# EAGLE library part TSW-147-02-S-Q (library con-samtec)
THROUGH-HOLE .025" SQ POST HEADER Source: Samtec TSW.pdf
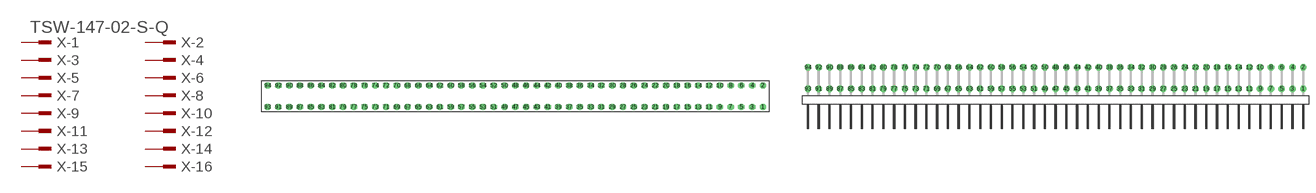
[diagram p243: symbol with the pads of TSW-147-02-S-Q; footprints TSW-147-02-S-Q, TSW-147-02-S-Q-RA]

Designator prefix X; gates -1=MPINV -2=MPIN -3=MPIN -4=MPIN -5=MPIN -6=MPIN -7=MPIN -8=MPIN -9=MPIN -10=MPIN -11=MPIN -12=MPIN -13=MPIN -14=MPIN -15=MPIN -16=MPIN -17=MPIN -18=MPIN -19=MPIN -20=MPIN -21=MPIN -22=MPIN -23=MPIN -24=MPIN -25=MPIN -26=MPIN -27=MPIN -28=MPIN -29=MPIN -30=MPIN -31=MPIN -32=MPIN -33=MPIN -34=MPIN -35=MPIN -36=MPIN -37=MPIN -38=MPIN -39=MPIN -40=MPIN -41=MPIN -42=MPIN -43=MPIN -44=MPIN -45=MPIN -46=MPIN -47=MPIN -48=MPIN -49=MPIN -50=MPIN -51=MPIN -52=MPIN -53=MPIN -54=MPIN -55=MPIN -56=MPIN -57=MPIN -58=MPIN -59=MPIN -60=MPIN -61=MPIN -62=MPIN -63=MPIN -64=MPIN -65=MPIN -66=MPIN -67=MPIN -68=MPIN -69=MPIN -70=MPIN -71=MPIN -72=MPIN -73=MPIN -74=MPIN -75=MPIN -76=MPIN -77=MPIN -78=MPIN -79=MPIN -80=MPIN -81=MPIN -82=MPIN -83=MPIN -84=MPIN -85=MPIN -86=MPIN -87=MPIN -88=MPIN -89=MPIN -90=MPIN -91=MPIN -92=MPIN -93=MPIN -94=MPIN

## TSW-147-02-S-Q (OC_FARNELL: unknown; OC_NEWARK: unknown)  [TSW-147-02-S-Q]
1  -1:1  pas
2  -2:1  pas
3  -3:1  pas
4  -4:1  pas
5  -5:1  pas
6  -6:1  pas
7  -7:1  pas
8  -8:1  pas
9  -9:1  pas
10  -10:1  pas
11  -11:1  pas
12  -12:1  pas
13  -13:1  pas
14  -14:1  pas
15  -15:1  pas
16  -16:1  pas
17  -17:1  pas
18  -18:1  pas
19  -19:1  pas
20  -20:1  pas
21  -21:1  pas
22  -22:1  pas
23  -23:1  pas
24  -24:1  pas
25  -25:1  pas
26  -26:1  pas
27  -27:1  pas
28  -28:1  pas
29  -29:1  pas
30  -30:1  pas
31  -31:1  pas
32  -32:1  pas
33  -33:1  pas
34  -34:1  pas
35  -35:1  pas
36  -36:1  pas
37  -37:1  pas
38  -38:1  pas
39  -39:1  pas
40  -40:1  pas
41  -41:1  pas
42  -42:1  pas
43  -43:1  pas
44  -44:1  pas
45  -45:1  pas
46  -46:1  pas
47  -47:1  pas
48  -48:1  pas
49  -49:1  pas
50  -50:1  pas
51  -51:1  pas
52  -52:1  pas
53  -53:1  pas
54  -54:1  pas
55  -55:1  pas
56  -56:1  pas
57  -57:1  pas
58  -58:1  pas
59  -59:1  pas
60  -60:1  pas
61  -61:1  pas
62  -62:1  pas
63  -63:1  pas
64  -64:1  pas
65  -65:1  pas
66  -66:1  pas
67  -67:1  pas
68  -68:1  pas
69  -69:1  pas
70  -70:1  pas
71  -71:1  pas
72  -72:1  pas
73  -73:1  pas
74  -74:1  pas
75  -75:1  pas
76  -76:1  pas
77  -77:1  pas
78  -78:1  pas
79  -79:1  pas
80  -80:1  pas
81  -81:1  pas
82  -82:1  pas
83  -83:1  pas
84  -84:1  pas
85  -85:1  pas
86  -86:1  pas
87  -87:1  pas
88  -88:1  pas
89  -89:1  pas
90  -90:1  pas
91  -91:1  pas
92  -92:1  pas
93  -93:1  pas
94  -94:1  pas

## TSW-147-02-S-Q-RA (OC_FARNELL: unknown; OC_NEWARK: unknown)  [TSW-147-02-S-Q-RA]
Pads as for TSW-147-02-S-Q

## Footprint TSW-147-02-S-Q (pad centres in mm)
THROUGH-HOLE .025" SQ POST HEADER Source: Samtec TSW.pdf
drill 1 pad 1.5 octagon: 1 58.42,-2.54; 2 58.42,2.54; 3 55.88,-2.54; 4 55.88,2.54; 5 53.34,-2.54; 6 53.34,2.54; 7 50.8,-2.54; 8 50.8,2.54; 9 48.26,-2.54; 10 48.26,2.54; 11 45.72,-2.54; 12 45.72,2.54; 13 43.18,-2.54; 14 43.18,2.54; 15 40.64,-2.54; 16 40.64,2.54; 17 38.1,-2.54; 18 38.1,2.54; 19 35.56,-2.54; 20 35.56,2.54; 21 33.02,-2.54; 22 33.02,2.54; 23 30.48,-2.54; 24 30.48,2.54; 25 27.94,-2.54; 26 27.94,2.54; 27 25.4,-2.54; 28 25.4,2.54; 29 22.86,-2.54; 30 22.86,2.54; 31 20.32,-2.54; 32 20.32,2.54; 33 17.78,-2.54; 34 17.78,2.54; 35 15.24,-2.54; 36 15.24,2.54; 37 12.7,-2.54; 38 12.7,2.54; 39 10.16,-2.54; 40 10.16,2.54; 41 7.62,-2.54; 42 7.62,2.54; 43 5.08,-2.54; 44 5.08,2.54; 45 2.54,-2.54; 46 2.54,2.54; 47 0,-2.54; 48 0,2.54; 49 -2.54,-2.54; 50 -2.54,2.54; 51 -5.08,-2.54; 52 -5.08,2.54; 53 -7.62,-2.54; 54 -7.62,2.54; 55 -10.16,-2.54; 56 -10.16,2.54; 57 -12.7,-2.54; 58 -12.7,2.54; 59 -15.24,-2.54; 60 -15.24,2.54; 61 -17.78,-2.54; 62 -17.78,2.54; 63 -20.32,-2.54; 64 -20.32,2.54; 65 -22.86,-2.54; 66 -22.86,2.54; 67 -25.4,-2.54; 68 -25.4,2.54; 69 -27.94,-2.54; 70 -27.94,2.54; 71 -30.48,-2.54; 72 -30.48,2.54; 73 -33.02,-2.54; 74 -33.02,2.54; 75 -35.56,-2.54; 76 -35.56,2.54; 77 -38.1,-2.54; 78 -38.1,2.54; 79 -40.64,-2.54; 80 -40.64,2.54; 81 -43.18,-2.54; 82 -43.18,2.54; 83 -45.72,-2.54; 84 -45.72,2.54; 85 -48.26,-2.54; 86 -48.26,2.54; 87 -50.8,-2.54; 88 -50.8,2.54; 89 -53.34,-2.54; 90 -53.34,2.54; 91 -55.88,-2.54; 92 -55.88,2.54; 93 -58.42,-2.54; 94 -58.42,2.54

## Footprint TSW-147-02-S-Q-RA (pad centres in mm)
THROUGH-HOLE .025" SQ POST HEADER Source: Samtec TSW.pdf
drill 1 pad 1.5 octagon: 1 58.42,1.524; 2 58.42,6.604; 3 55.88,1.524; 4 55.88,6.604; 5 53.34,1.524; 6 53.34,6.604; 7 50.8,1.524; 8 50.8,6.604; 9 48.26,1.524; 10 48.26,6.604; 11 45.72,1.524; 12 45.72,6.604; 13 43.18,1.524; 14 43.18,6.604; 15 40.64,1.524; 16 40.64,6.604; 17 38.1,1.524; 18 38.1,6.604; 19 35.56,1.524; 20 35.56,6.604; 21 33.02,1.524; 22 33.02,6.604; 23 30.48,1.524; 24 30.48,6.604; 25 27.94,1.524; 26 27.94,6.604; 27 25.4,1.524; 28 25.4,6.604; 29 22.86,1.524; 30 22.86,6.604; 31 20.32,1.524; 32 20.32,6.604; 33 17.78,1.524; 34 17.78,6.604; 35 15.24,1.524; 36 15.24,6.604; 37 12.7,1.524; 38 12.7,6.604; 39 10.16,1.524; 40 10.16,6.604; 41 7.62,1.524; 42 7.62,6.604; 43 5.08,1.524; 44 5.08,6.604; 45 2.54,1.524; 46 2.54,6.604; 47 0,1.524; 48 0,6.604; 49 -2.54,1.524; 50 -2.54,6.604; 51 -5.08,1.524; 52 -5.08,6.604; 53 -7.62,1.524; 54 -7.62,6.604; 55 -10.16,1.524; 56 -10.16,6.604; 57 -12.7,1.524; 58 -12.7,6.604; 59 -15.24,1.524; 60 -15.24,6.604; 61 -17.78,1.524; 62 -17.78,6.604; 63 -20.32,1.524; 64 -20.32,6.604; 65 -22.86,1.524; 66 -22.86,6.604; 67 -25.4,1.524; 68 -25.4,6.604; 69 -27.94,1.524; 70 -27.94,6.604; 71 -30.48,1.524; 72 -30.48,6.604; 73 -33.02,1.524; 74 -33.02,6.604; 75 -35.56,1.524; 76 -35.56,6.604; 77 -38.1,1.524; 78 -38.1,6.604; 79 -40.64,1.524; 80 -40.64,6.604; 81 -43.18,1.524; 82 -43.18,6.604; 83 -45.72,1.524; 84 -45.72,6.604; 85 -48.26,1.524; 86 -48.26,6.604; 87 -50.8,1.524; 88 -50.8,6.604; 89 -53.34,1.524; 90 -53.34,6.604; 91 -55.88,1.524; 92 -55.88,6.604; 93 -58.42,1.524; 94 -58.42,6.604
